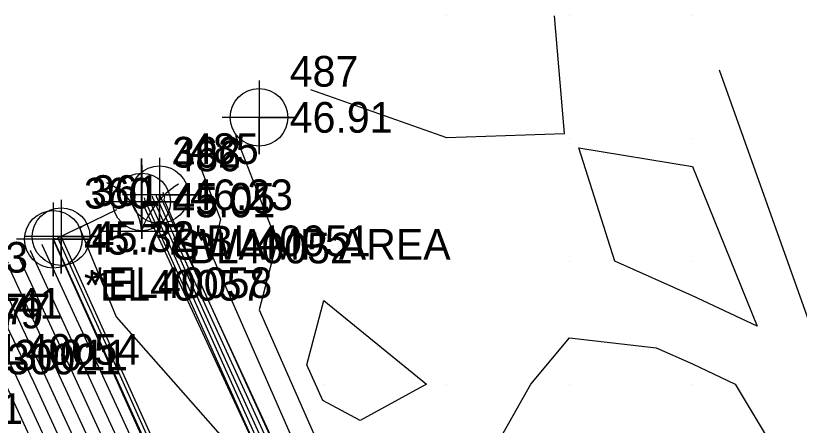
# Model space of a CAD drawing. Extents: x 2090860 to 2091277, y 159470 to 160080.
# Drawn here: x 2090944.9 to 2091008.7, y 160046.6 to 160080 of the extents above; entities that cross this region are included whole.
import ezdxf

# ---------------------------------------------------------------- set-up
doc = ezdxf.new("R2010")
doc.units = 0
for name, color, linetype in [('DTM Contours Major', 7, 'Continuous'), ('DTM Contours Minor', 7, 'Continuous'), ('Exist DTM Breakline', 7, 'Continuous'), ('Exist DTM Breakline Cogo Comment', 7, 'Continuous'), ('Exist DTM Breakline Cogo Elevation', 7, 'Continuous'), ('Exist DTM Breakline Cogo Number', 7, 'Continuous'), ('Exist DTM Breakline Cogo Point CELL', 7, 'Continuous'), ('Exist DTM Crownline Cogo Comment', 7, 'Continuous'), ('Exist DTM QL2 LIDAR Elevation Point', 7, 'Continuous'), ('Exist DTM Regular Point CELL', 7, 'Continuous'), ('Exist DTM Regular Point Cogo Elevation', 7, 'Continuous'), ('Exist DTM Regular Point Cogo Number', 7, 'Continuous'), ('Exist Hydro Swamp or Marsh', 7, 'Continuous'), ('Exist Hydro Swamp or Marsh Cogo Comment', 7, 'Continuous'), ('Exist Hydro Swamp or Marsh Cogo Elevation', 7, 'Continuous'), ('Exist Hydro Swamp or Marsh Cogo Number', 7, 'Continuous'), ('Exist Roads EOP Cogo Comment', 7, 'Continuous'), ('Exist Roads EOP Cogo Elevation', 7, 'Continuous'), ('Exist Roads EOT Cogo Comment', 7, 'Continuous'), ('Exist Roads EOT Cogo Elevation', 7, 'Continuous')]:
    doc.layers.add(name, color=color, linetype=linetype)

msp = doc.modelspace()

# ---------------------------------------------------------------- linework, layer by layer
at = {"layer": 'DTM Contours Major'}
for points in [[(2090968.904, 160073.985), (2090980, 160070.084), (2090989.583, 160070.417), (2090988.779, 160080)], [(2091000, 160057.196), (2090993.684, 160060), (2090990.755, 160069.245), (2091000, 160067.709), (2091005.287, 160054.713), (2091000, 160057.196)], [(2090956.341, 160065.361), (2090956.351, 160065.306), (2090959.29, 160058.77), (2090968.77, 160038.007), (2090971.862, 160031.101), (2090977.516, 160018.706), (2090978.126, 160018.174), (2090989.29, 159992.953), (2090989.994, 159992.181), (2090990.384, 159991.663), (2090990.651, 159991.238), (2090998.867, 159980.879), (2091008.192, 159981.808), (2091007.743, 159990), (2091008.559, 159991.441), (2091010, 159993.309)], [(2091021.025, 159898.877), (2091011.639, 159919.455), (2091005.482, 159932.957), (2091005.012, 159933.952), (2090993.094, 159961.193), (2090992.991, 159961.428), (2090991.418, 159965.023), (2090992.968, 159961.452), (2090985.925, 159965.485), (2090984.33, 159968.87), (2090979.616, 159978.837), (2090976.348, 159997.974), (2090975.965, 159998.781), (2090963.783, 160025.207), (2090963.068, 160026.714), (2090951.202, 160052.433), (2090950.873, 160053.127), (2090947.083, 160061.339), (2090947.113, 160061.357)], [(2091021.18, 159890.907), (2091013.639, 159907.174), (2091008.516, 159918.108), (2091005.725, 159924.066), (2091001.855, 159932.408), (2090996.755, 159943.477), (2090989.564, 159959.773), (2090985.428, 159962.142), (2090982.708, 159967.911), (2090974.675, 159984.898), (2090972.744, 159996.202), (2090967.23, 160007.833), (2090960.061, 160023.383), (2090954.323, 160035.484), (2090947.368, 160050.56), (2090945.472, 160054.558), (2090943.253, 160059.365), (2090943.413, 160059.46)], [(2090968.63, 160051.579), (2090970, 160056.798), (2090978.351, 160050), (2090972.963, 160047.037), (2090969.908, 160048.671), (2090968.63, 160051.579)]]:
    msp.add_lwpolyline(points, dxfattribs=at)
at = {"layer": 'DTM Contours Minor'}
for points in [[(2091012.814, 160045.779), (2091002.223, 160075.555)], [(2090962.817, 160070.236), (2090966.182, 160061.546), (2090964.741, 160056.06), (2090969.648, 160044.9), (2090979.093, 160039.847), (2090975.783, 160033.187), (2090979.196, 160025.31), (2090986.367, 160023.633), (2090990, 160023.404), (2090995.039, 160024.961), (2090998.841, 160030), (2090991.992, 160034.585), (2090981.432, 160039.992), (2090982.77, 160042.77), (2090986.859, 160050), (2090990, 160053.765), (2090997.048, 160052.952), (2091000, 160051.642), (2091003.496, 160050), (2091008.694, 160041.306), (2091009.539, 160039.998), (2091007.882, 160037.882), (2091008.162, 160030), (2091010, 160029.803)], [(2090959.85, 160067.927), (2090961.603, 160063.399), (2090960.853, 160060.541), (2090969.388, 160041.128), (2090973.538, 160038.908), (2090972.083, 160035.982), (2090978.491, 160021.196), (2090985.462, 160019.565), (2090990, 160012.68), (2090994.856, 160015.144), (2090995.921, 160020), (2090999.037, 160020.963), (2091000, 160022.239), (2091004.956, 160025.044), (2091010, 160024.503), (2091013.768, 160026.232), (2091016.326, 160030), (2091016.342, 160033.658), (2091017.201, 160035.597), (2091017.93, 160038.105), (2091010.492, 160059.017)], [(2090956.883, 160065.619), (2090957.025, 160065.253), (2090956.964, 160065.022), (2090960.254, 160057.54), (2090969.111, 160038.143), (2090969.661, 160036.915), (2090977.917, 160018.813), (2090978.101, 160018.652), (2090981.469, 160011.044), (2090989.997, 160001.7), (2090994.717, 159995.42), (2090997.946, 159990.272), (2090999.751, 159987.996), (2091001.8, 159988.2), (2091001.701, 159990), (2091004.702, 159995.298), (2091008.33, 160000), (2091007.204, 160002.796), (2091009.862, 160010)], [(2090953.131, 160064.189), (2090950.324, 160062.823), (2090950.15, 160062.668), (2090953.104, 160055.485), (2090966.615, 160040.133), (2090955.458, 160064.946), (2090955.415, 160065.18)], [(2090955.723, 160065.24), (2090955.755, 160065.066), (2090965.14, 160044.195), (2090968.09, 160037.734), (2090976.266, 160019.474), (2090976.714, 160018.492), (2090978.176, 160017.217), (2090985.815, 159999.959), (2090989.474, 159991.243), (2090993.478, 159982.712), (2090997.759, 159973.016), (2091003.522, 159962), (2091011.65, 159946.449)], [(2090956.032, 160065.301), (2090956.053, 160065.186), (2090962.215, 160051.483), (2090968.43, 160037.87), (2090974.064, 160025.288), (2090977.115, 160018.599), (2090978.151, 160017.695), (2090988.003, 159995.439), (2090989.746, 159991.286), (2090991.654, 159987.221), (2090997.113, 159974.859), (2090997.983, 159973.762), (2090999.376, 159973.9), (2091008.084, 159970.483), (2091003.919, 159961.557), (2091011.802, 159946.475)], [(2091025.102, 159892.473), (2091012.728, 159918.738), (2091012.329, 159919.613), (2091012.067, 159920.187), (2091005.42, 159934.274), (2091005.163, 159934.86), (2090993.441, 159961.728), (2090992.08, 159964.838), (2090989.382, 159971.02), (2090984.007, 159982.894), (2090977.042, 159998.364), (2090971.588, 160010.408), (2090964.702, 160025.709), (2090959.133, 160037.996), (2090952.362, 160053.053), (2090950.665, 160056.795), (2090948.359, 160061.924), (2090950.641, 160063.035)], [(2091024.64, 159892.328), (2091016.876, 159908.808), (2091011.984, 159919.534), (2091008.774, 159926.572), (2091005.216, 159934.113), (2090999.129, 159948.027), (2090993.216, 159961.578), (2090990.478, 159967.834), (2090989.149, 159970.881), (2090979.664, 159991.834), (2090976.792, 159998.213), (2090966.504, 160020.929), (2090964.429, 160025.539), (2090952.994, 160050.772), (2090952.056, 160052.858), (2090948.153, 160061.461), (2090947.998, 160061.806), (2090948.151, 160061.88)], [(2091023.606, 159891.972), (2091011.906, 159917.209), (2091010.978, 159919.19), (2091010.473, 159920.269), (2091004.292, 159933.592), (2091003.168, 159936.032), (2090992.143, 159961.018), (2090985.801, 159964.649), (2090983.924, 159968.63), (2090978.381, 159980.353), (2090975.447, 159997.531), (2090973.781, 160001.044), (2090962.852, 160024.751), (2090960.882, 160028.906), (2090950.243, 160051.965), (2090949.523, 160053.484), (2090946.126, 160060.846), (2090946.188, 160060.883)], [(2091021.989, 159891.262), (2091013.061, 159910.519), (2091009.337, 159918.469), (2091007.307, 159922.8), (2091002.667, 159932.803), (2090998.893, 159940.995), (2090990.424, 159960.188), (2090985.552, 159962.978), (2090983.114, 159968.151), (2090975.91, 159983.383), (2090973.645, 159996.645), (2090969.414, 160005.57), (2090960.992, 160023.839), (2090956.509, 160033.292), (2090948.326, 160051.028), (2090946.822, 160054.2), (2090944.211, 160059.859), (2090944.338, 160059.934)], [(2091022.798, 159891.617), (2091012.484, 159913.864), (2091010.158, 159918.829), (2091008.89, 159921.535), (2091003.48, 159933.198), (2091001.03, 159938.513), (2090991.283, 159960.603), (2090985.677, 159963.813), (2090983.519, 159968.391), (2090977.145, 159981.868), (2090974.546, 159997.088), (2090971.598, 160003.307), (2090961.922, 160024.295), (2090958.696, 160031.099), (2090949.285, 160051.497), (2090948.173, 160053.842), (2090945.168, 160060.352), (2090945.263, 160060.408)], [(2091014.217, 159903.829), (2091007.695, 159917.748), (2091004.142, 159925.332), (2091001.042, 159932.013), (2090994.617, 159945.959), (2090988.704, 159959.359), (2090985.303, 159961.306), (2090982.303, 159967.671), (2090973.44, 159986.413), (2090971.844, 159995.759), (2090965.046, 160010.096), (2090959.131, 160022.927), (2090952.137, 160037.677), (2090946.409, 160050.092), (2090944.121, 160054.915), (2090942.296, 160058.872), (2090942.487, 160058.986)], [(2091015.372, 159897.139), (2091006.054, 159917.027), (2091000.976, 159927.863), (2090999.417, 159931.224), (2090990.342, 159950.923), (2090986.985, 159958.529), (2090985.054, 159959.635), (2090981.492, 159967.192), (2090970.969, 159989.443), (2090970.042, 159994.873), (2090960.679, 160014.622), (2090957.27, 160022.016), (2090947.764, 160042.063), (2090944.492, 160049.155), (2090941.421, 160055.631), (2090940.381, 160057.885), (2090940.637, 160058.037)], [(2091014.794, 159900.484), (2091006.874, 159917.387), (2091002.559, 159926.597), (2091000.23, 159931.619), (2090992.479, 159948.441), (2090987.845, 159958.944), (2090985.179, 159960.47), (2090981.898, 159967.432), (2090972.204, 159987.928), (2090970.943, 159995.316), (2090962.863, 160012.359), (2090958.2, 160022.472), (2090949.95, 160039.87), (2090945.45, 160049.623), (2090942.771, 160055.273), (2090941.338, 160058.378), (2090941.562, 160058.512)]]:
    msp.add_lwpolyline(points, dxfattribs=at)
at = {"layer": 'Exist DTM Breakline'}
for points in [[(2090956.622, 160065.416), (2090978.09, 160018.859), (2090997.895, 159973.05), (2091025.359, 159920.65)], [(2090955.177, 160064.832), (2090976.645, 160018.474), (2090997.432, 159972.935), (2091025.272, 159920.294)], [(2091060.143, 159819.743), (2091040.416, 159857.574), (2091023.862, 159892.084), (2091004.981, 159933.927), (2090988.922, 159970.746), (2090947.972, 160061.797)], [(2091061.634, 159820.633), (2091041.562, 159858.316), (2091025.181, 159892.498), (2091005.429, 159934.281), (2090989.687, 159971.201), (2090948.616, 160062.008)]]:
    msp.add_lwpolyline(points, dxfattribs=at)
at = {"layer": 'Exist DTM Breakline Cogo Point CELL'}
for points in [[(2090956.622, 160068.416), (2090956.622, 160062.416), (2090956.622, 160065.416), (2090959.622, 160065.416), (2090953.622, 160065.416)], [(2090955.177, 160067.832), (2090955.177, 160061.832), (2090955.177, 160064.832), (2090958.177, 160064.832), (2090952.177, 160064.832)], [(2090948.616, 160065.008), (2090948.616, 160059.008), (2090948.616, 160062.008), (2090951.616, 160062.008), (2090945.616, 160062.008)], [(2090947.972, 160064.797), (2090947.972, 160058.797), (2090947.972, 160061.797), (2090950.972, 160061.797), (2090944.972, 160061.797)]]:
    msp.add_lwpolyline(points, dxfattribs=at)
for centre in [(2090956.622, 160065.416), (2090955.177, 160064.832), (2090948.616, 160062.008), (2090947.972, 160061.797)]:
    msp.add_circle(centre, 2.344, dxfattribs=at)
at = {"layer": 'Exist DTM QL2 LIDAR Elevation Point'}
for p, q in [((2090980, 160080), (2090980, 160080)), ((2090990, 160080), (2090990, 160080)), ((2091000, 160080), (2091000, 160080)), ((2090980, 160070), (2090980, 160070)), ((2090990, 160070), (2090990, 160070)), ((2091000, 160070), (2091000, 160070)), ((2090970, 160060), (2090970, 160060)), ((2090980, 160060), (2090980, 160060)), ((2090990, 160060), (2090990, 160060)), ((2091000, 160060), (2091000, 160060)), ((2090970, 160050), (2090970, 160050)), ((2090980, 160050), (2090980, 160050)), ((2090990, 160050), (2090990, 160050)), ((2091000, 160050), (2091000, 160050))]:
    msp.add_line(p, q, dxfattribs=at)
at = {"layer": 'Exist DTM Regular Point CELL'}
msp.add_lwpolyline([(2090964.728, 160074.722), (2090964.728, 160068.722), (2090964.728, 160071.722), (2090967.728, 160071.722), (2090961.728, 160071.722)], dxfattribs=at)
msp.add_circle((2090964.728, 160071.722), 2.344, dxfattribs=at)
at = {"layer": 'Exist Hydro Swamp or Marsh'}
msp.add_line((2090955.163, 160065.131), (2090955.163, 160065.131), dxfattribs=at)
msp.add_lwpolyline([(2090951.938, 160062.457), (2090955.164, 160062.457), (2090955.164, 160068.374), (2090955.164, 160062.457), (2090958.389, 160062.457)], dxfattribs=at)
for centre, radius, start, end in [((2090950.564, 160062.124), 4.612, 4.14034, 67.53497), ((2090962.005, 160060.184), 7.208, 122.12745, 161.62219)]:
    msp.add_arc(centre, radius, start, end, dxfattribs=at)

# ---------------------------------------------------------------- texts
at = {"layer": 'Exist DTM Breakline Cogo Comment'}
for s, p in [('*BL40051', (2090959.122, 160060.416)), ('*BL40052', (2090957.677, 160059.832)), ('*EL40057', (2090950.472, 160056.797)), ('*EL40058', (2090951.116, 160057.008)), ('*EL40054', (2090940.345, 160051.578))]:
    msp.add_text(s, height=2.5, dxfattribs=at).set_placement(p)
at = {"layer": 'Exist DTM Breakline Cogo Elevation'}
for s, p in [('46.23', (2090959.122, 160064.166)), ('45.01', (2090957.677, 160063.582)), ('45.32', (2090951.116, 160060.758)), ('45.77', (2090950.472, 160060.547)), ('48.41', (2090940.345, 160055.328))]:
    msp.add_text(s, height=2.5, dxfattribs=at).set_placement(p)
at = {"layer": 'Exist DTM Breakline Cogo Number'}
for s, p in [('485', (2090959.122, 160067.916)), ('486', (2090957.677, 160067.332)), ('361', (2090951.116, 160064.508)), ('360', (2090950.472, 160064.297)), ('363', (2090940.345, 160059.078))]:
    msp.add_text(s, height=2.5, dxfattribs=at).set_placement(p)
at = {"layer": 'Exist DTM Crownline Cogo Comment'}
msp.add_text('*EL30081', height=2.5, dxfattribs=at).set_placement((2090930.833, 160046.748))
at = {"layer": 'Exist DTM Regular Point Cogo Elevation'}
msp.add_text('46.91', height=2.5, dxfattribs=at).set_placement((2090967.228, 160070.472))
at = {"layer": 'Exist DTM Regular Point Cogo Number'}
msp.add_text('487', height=2.5, dxfattribs=at).set_placement((2090967.228, 160074.222))
at = {"layer": 'Exist Hydro Swamp or Marsh Cogo Comment'}
msp.add_text('SWAMP AREA', height=2.5, dxfattribs=at).set_placement((2090957.663, 160060.131))
at = {"layer": 'Exist Hydro Swamp or Marsh Cogo Elevation'}
msp.add_text('45.05', height=2.5, dxfattribs=at).set_placement((2090957.663, 160063.881))
at = {"layer": 'Exist Hydro Swamp or Marsh Cogo Number'}
msp.add_text('362', height=2.5, dxfattribs=at).set_placement((2090957.663, 160067.631))
at = {"layer": 'Exist Roads EOP Cogo Comment'}
msp.add_text('*EL30011', height=2.5, dxfattribs=at).set_placement((2090939.377, 160051.11))
at = {"layer": 'Exist Roads EOP Cogo Elevation'}
msp.add_text('48.77', height=2.5, dxfattribs=at).set_placement((2090939.377, 160054.86))
at = {"layer": 'Exist Roads EOT Cogo Comment'}
for p in [(2090938.796, 160050.791), (2090930.833, 160046.748)]:
    msp.add_text('*EL30021', height=2.5, dxfattribs=at).set_placement(p)
at = {"layer": 'Exist Roads EOT Cogo Elevation'}
msp.add_text('48.79', height=2.5, dxfattribs=at).set_placement((2090938.796, 160054.541))

doc.saveas('drawing.dxf')
